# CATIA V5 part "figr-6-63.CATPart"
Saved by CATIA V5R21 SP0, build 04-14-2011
Part number: Part1
Bounding box of the stored display mesh (mm): x -50.648 to 96.836, y -72.183 to 72.183, z -40 to 40
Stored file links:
  D:\CATIA V5R21 E-RESOURCES\CATIA-V5R21\catia-v5r21-prt\c06-catia-v5r21-prt\c06-catia-v5r21-figr-6-63.CATPart
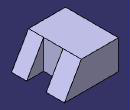
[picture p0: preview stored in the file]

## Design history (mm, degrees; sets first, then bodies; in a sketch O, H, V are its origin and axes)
Set1
  Plane1: type Offset, RefPlane face of Pad1, Offset -50, reversed
  Plane2: type Offset, RefPlane Plane1, Offset 53
Body1 (main body)
  Sketch1 on xy-plane, origin (0, 0, 0), H (1, 0, 0), V (0, 1, 0)
    line L1 (-50.6478, 72.1832) -> (50.6478, 72.1832)
    line L2 (50.6478, 72.1832) -> (50.6478, -72.1832)
    line L3 (50.6478, -72.1832) -> (-50.6478, -72.1832)
    line L4 (-50.6478, -72.1832) -> (-50.6478, 72.1832)
    axis line L5 (50.6478, -72.1832) -> (-50.6478, 72.1832)
    horizontal: L1 H, L3 H
    vertical: L2 V, L4 V
    midpoint: O L5
  Pad1: profile Sketch1, direction (0, 0, 1), length 40, mirrored extent
  Draft1: Angle 30, Neutral face of Pad1, PullDir (0, 0, 1), SupportToDraft face of Pad1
